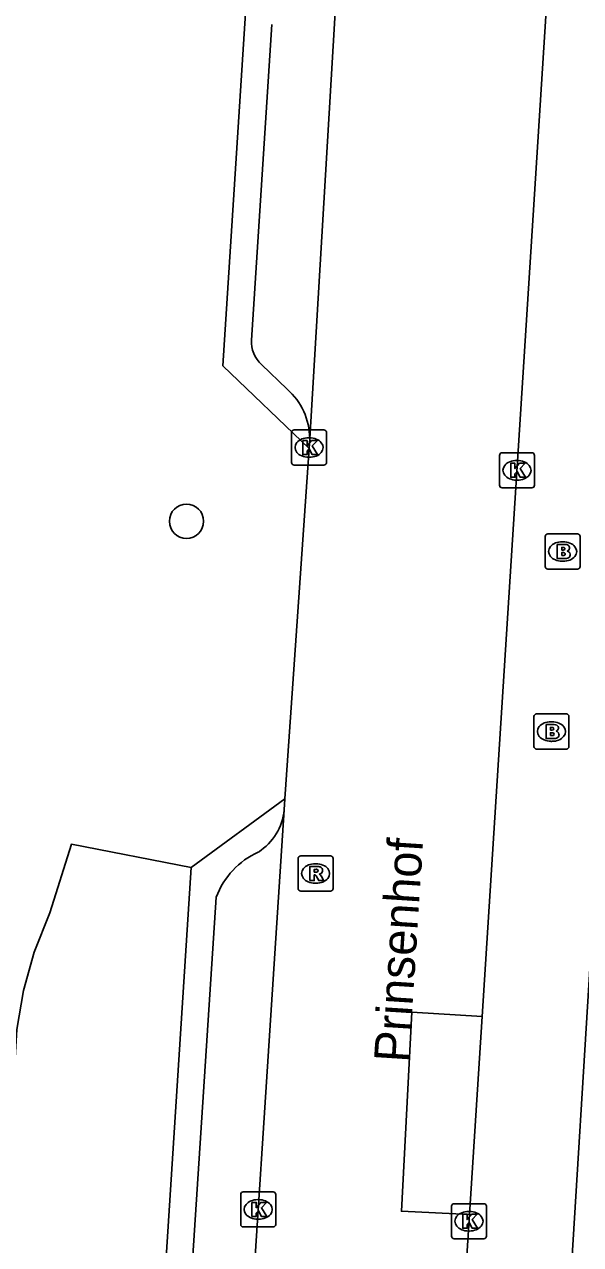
# Model space of a CAD drawing. Extents: x 159961 to 160856, y 382704 to 383353.
# Drawn here: x 160609.97 to 160625.85, y 382840.38 to 382875.2 of the extents above; entities that cross this region are included whole.
import ezdxf

# ---------------------------------------------------------------- set-up
doc = ezdxf.new("R2010")
doc.units = 0
for name, color, linetype in [('IMGEO_Boom', 7, 'Continuous'), ('IMGEO_Brandkraan', 7, 'Continuous'), ('IMGEO_Groenvoorziening', 7, 'Continuous'), ('IMGEO_Kolk', 7, 'Continuous'), ('IMGEO_Openbare_ruimte_label', 7, 'Continuous'), ('IMGEO_Rijbaan_lokaal_open', 7, 'Continuous'), ('IMGEO_Rioolput', 7, 'Continuous'), ('IMGEO_Voetpad_open', 7, 'Continuous')]:
    doc.layers.add(name, color=color, linetype=linetype)

msp = doc.modelspace()

# ---------------------------------------------------------------- linework, layer by layer
at = {"layer": 'IMGEO_Boom'}
msp.add_circle((160614.596, 382861.021), 0.489, dxfattribs=at)
at = {"layer": 'IMGEO_Brandkraan'}
for p, q in [((160624.836, 382859.731), (160624.836, 382860.583)), ((160624.911, 382860.657), (160625.763, 382860.657)), ((160625.324, 382860.437), (160625.349, 382860.437)), ((160625.837, 382860.583), (160625.837, 382859.731)), ((160625.763, 382859.657), (160624.911, 382859.657)), ((160625.347, 382859.877), (160625.322, 382859.877)), ((160624.591, 382855.521), (160625.443, 382855.521)), ((160624.516, 382854.595), (160624.516, 382855.447)), ((160625.004, 382855.301), (160625.029, 382855.301)), ((160625.517, 382855.447), (160625.517, 382854.595)), ((160625.443, 382854.521), (160624.591, 382854.521)), ((160625.027, 382854.741), (160625.002, 382854.741))]:
    msp.add_line(p, q, dxfattribs=at)
for points in [[(160624.836, 382859.731), (160624.836, 382860.583)], [(160624.911, 382860.657), (160625.763, 382860.657)], [(160625.184, 382860.357), (160625.184, 382859.957), (160625.397, 382859.957)], [(160625.415, 382860.357), (160625.184, 382860.357)], [(160625.837, 382860.583), (160625.837, 382859.731)], [(160625.363, 382860.276), (160625.309, 382860.276), (160625.309, 382860.2)], [(160625.309, 382860.2), (160625.362, 382860.2)], [(160625.371, 382860.124), (160625.309, 382860.124), (160625.309, 382860.043)], [(160625.309, 382860.043), (160625.371, 382860.043)], [(160625.763, 382859.657), (160624.911, 382859.657)], [(160624.591, 382855.521), (160625.443, 382855.521)], [(160624.516, 382854.595), (160624.516, 382855.447)], [(160624.864, 382855.221), (160624.864, 382854.821), (160625.077, 382854.821)], [(160625.095, 382855.221), (160624.864, 382855.221)], [(160625.043, 382855.14), (160624.989, 382855.14), (160624.989, 382855.064)], [(160625.517, 382855.447), (160625.517, 382854.595)], [(160624.989, 382855.064), (160625.042, 382855.064)], [(160625.051, 382854.988), (160624.989, 382854.988), (160624.989, 382854.907)], [(160624.989, 382854.907), (160625.051, 382854.907)], [(160625.443, 382854.521), (160624.591, 382854.521)]]:
    msp.add_lwpolyline(points, dxfattribs=at)
for centre, radius, start, end in [((160624.913, 382860.581), 0.0765, 91.552, 178.448), ((160624.913, 382860.581), 0.0765, 91.552, 178.448), ((160625.419, 382860.212), 0.145, 59.4692, 91.5367), ((160625.444, 382860.259), 0.0922, 285.5137, 58.1501), ((160625.761, 382860.581), 0.0765, 1.552, 88.448), ((160625.761, 382860.581), 0.0765, 1.552, 88.448), ((160625.364, 382860.238), 0.0379, 267.8285, 90.9355), ((160625.372, 382860.083), 0.0404, 269.8759, 90.5077), ((160625.449, 382860.067), 0.105, 301.3115, 78.989), ((160624.913, 382859.733), 0.0765, 181.552, 268.448), ((160624.913, 382859.733), 0.0765, 181.552, 268.448), ((160625.403, 382860.208), 0.251, 268.6676, 293.5347), ((160625.761, 382859.733), 0.0765, 271.552, 358.448), ((160625.761, 382859.733), 0.0765, 271.552, 358.448), ((160624.593, 382855.445), 0.0765, 91.552, 178.448), ((160624.593, 382855.445), 0.0765, 91.552, 178.448), ((160625.441, 382855.445), 0.0765, 1.552, 88.448), ((160625.441, 382855.445), 0.0765, 1.552, 88.448), ((160625.044, 382855.102), 0.0379, 267.8285, 90.9355), ((160625.099, 382855.076), 0.145, 59.4692, 91.5367), ((160625.124, 382855.123), 0.0922, 285.5137, 58.1501), ((160625.052, 382854.947), 0.0404, 269.8759, 90.5077), ((160625.083, 382855.072), 0.251, 268.6676, 293.5347), ((160625.129, 382854.931), 0.105, 301.3115, 78.989), ((160624.593, 382854.597), 0.0765, 181.552, 268.448), ((160624.593, 382854.597), 0.0765, 181.552, 268.448), ((160625.441, 382854.597), 0.0765, 271.552, 358.448), ((160625.441, 382854.597), 0.0765, 271.552, 358.448)]:
    msp.add_arc(centre, radius, start, end, dxfattribs=at)
for centre, major_axis, ratio, start_param, end_param in [((160625.323, 382860.157), (-0.387, 0.002), 0.722429, 4.712389, 7.853982), ((160625.348, 382860.157), (-0.39, 0.002), 0.717154, 1.570796, 4.712389), ((160625.003, 382855.021), (-0.387, 0.002), 0.722429, 4.712389, 7.853982), ((160625.028, 382855.021), (-0.39, 0.002), 0.717154, 1.570796, 4.712389)]:
    msp.add_ellipse(centre, major_axis=major_axis, ratio=ratio, start_param=start_param, end_param=end_param, dxfattribs=at)
at = {"layer": 'IMGEO_Groenvoorziening'}
msp.add_lwpolyline([(160601.528, 382813.411), (160601.58, 382813.752), (160601.524, 382815.216), (160601.773, 382816.66), (160602.317, 382818.02), (160603.033, 382819.117), (160607.251, 382823.714), (160607.533, 382824.104), (160607.967, 382824.962), (160608.26, 382826.337), (160609.182, 382837.25), (160609.683, 382845.386), (160609.753, 382846.515), (160609.94, 382847.631), (160610.243, 382848.721), (160610.693, 382849.85), (160611.309, 382851.803), (160614.727, 382851.14)], dxfattribs=at)
at = {"layer": 'IMGEO_Kolk'}
for p, q in [((160617.595, 382862.698), (160617.595, 382863.55)), ((160617.67, 382863.624), (160618.522, 382863.624)), ((160618.596, 382863.55), (160618.596, 382862.698)), ((160618.083, 382863.404), (160618.108, 382863.404)), ((160618.106, 382862.844), (160618.081, 382862.844)), ((160623.532, 382862.048), (160623.532, 382862.9)), ((160623.607, 382862.974), (160624.459, 382862.974)), ((160624.533, 382862.9), (160624.533, 382862.048)), ((160618.522, 382862.624), (160617.67, 382862.624)), ((160624.02, 382862.754), (160624.045, 382862.754)), ((160624.043, 382862.194), (160624.018, 382862.194)), ((160624.459, 382861.974), (160623.607, 382861.974)), ((160616.218, 382841.886), (160617.07, 382841.886)), ((160616.143, 382840.96), (160616.143, 382841.812)), ((160616.631, 382841.666), (160616.656, 382841.666)), ((160617.144, 382841.812), (160617.144, 382840.96)), ((160622.237, 382841.549), (160623.089, 382841.549)), ((160622.162, 382840.623), (160622.162, 382841.475)), ((160622.65, 382841.329), (160622.675, 382841.329)), ((160623.163, 382841.475), (160623.163, 382840.623)), ((160617.07, 382840.886), (160616.218, 382840.886)), ((160616.654, 382841.106), (160616.629, 382841.106)), ((160623.089, 382840.549), (160622.237, 382840.549)), ((160622.673, 382840.769), (160622.648, 382840.769))]:
    msp.add_line(p, q, dxfattribs=at)
for points in [[(160617.595, 382862.698), (160617.595, 382863.55)], [(160617.67, 382863.624), (160618.522, 382863.624)], [(160618.596, 382863.55), (160618.596, 382862.698)], [(160617.916, 382863.324), (160618.039, 382863.324), (160618.039, 382863.173), (160618.169, 382863.324), (160618.333, 382863.324), (160618.187, 382863.173), (160618.34, 382862.924), (160618.188, 382862.924), (160618.103, 382863.088), (160618.039, 382863.021), (160618.039, 382862.924), (160617.916, 382862.924), (160617.916, 382863.324)], [(160623.532, 382862.048), (160623.532, 382862.9)], [(160623.607, 382862.974), (160624.459, 382862.974)], [(160624.533, 382862.9), (160624.533, 382862.048)], [(160618.522, 382862.624), (160617.67, 382862.624)], [(160623.853, 382862.674), (160623.976, 382862.674), (160623.976, 382862.523), (160624.106, 382862.674), (160624.27, 382862.674), (160624.124, 382862.523), (160624.277, 382862.274), (160624.125, 382862.274), (160624.04, 382862.438), (160623.976, 382862.371), (160623.976, 382862.274), (160623.853, 382862.274), (160623.853, 382862.674)], [(160624.459, 382861.974), (160623.607, 382861.974)], [(160616.218, 382841.886), (160617.07, 382841.886)], [(160616.143, 382840.96), (160616.143, 382841.812)], [(160616.464, 382841.586), (160616.587, 382841.586), (160616.587, 382841.435), (160616.717, 382841.586), (160616.881, 382841.586), (160616.735, 382841.435), (160616.888, 382841.186), (160616.736, 382841.186), (160616.651, 382841.35), (160616.587, 382841.283), (160616.587, 382841.186), (160616.464, 382841.186), (160616.464, 382841.586)], [(160617.144, 382841.812), (160617.144, 382840.96)], [(160622.237, 382841.549), (160623.089, 382841.549)], [(160622.162, 382840.623), (160622.162, 382841.475)], [(160622.483, 382841.249), (160622.606, 382841.249), (160622.606, 382841.098), (160622.736, 382841.249), (160622.9, 382841.249), (160622.754, 382841.098), (160622.907, 382840.849), (160622.755, 382840.849), (160622.67, 382841.013), (160622.606, 382840.946), (160622.606, 382840.849), (160622.483, 382840.849), (160622.483, 382841.249)], [(160623.163, 382841.475), (160623.163, 382840.623)], [(160617.07, 382840.886), (160616.218, 382840.886)], [(160623.089, 382840.549), (160622.237, 382840.549)]]:
    msp.add_lwpolyline(points, dxfattribs=at)
for centre, start, end in [((160617.672, 382863.548), 91.552, 178.448), ((160617.672, 382863.548), 91.552, 178.448), ((160618.52, 382863.548), 1.552, 88.448), ((160618.52, 382863.548), 1.552, 88.448), ((160623.609, 382862.898), 91.552, 178.448), ((160623.609, 382862.898), 91.552, 178.448), ((160624.457, 382862.898), 1.552, 88.448), ((160624.457, 382862.898), 1.552, 88.448), ((160617.672, 382862.7), 181.552, 268.448), ((160617.672, 382862.7), 181.552, 268.448), ((160618.52, 382862.7), 271.552, 358.448), ((160618.52, 382862.7), 271.552, 358.448), ((160623.609, 382862.05), 181.552, 268.448), ((160623.609, 382862.05), 181.552, 268.448), ((160624.457, 382862.05), 271.552, 358.448), ((160624.457, 382862.05), 271.552, 358.448), ((160616.22, 382841.81), 91.552, 178.448), ((160616.22, 382841.81), 91.552, 178.448), ((160617.068, 382841.81), 1.552, 88.448), ((160617.068, 382841.81), 1.552, 88.448), ((160622.239, 382841.473), 91.552, 178.448), ((160622.239, 382841.473), 91.552, 178.448), ((160623.087, 382841.473), 1.552, 88.448), ((160623.087, 382841.473), 1.552, 88.448), ((160616.22, 382840.962), 181.552, 268.448), ((160616.22, 382840.962), 181.552, 268.448), ((160617.068, 382840.962), 271.552, 358.448), ((160617.068, 382840.962), 271.552, 358.448), ((160622.239, 382840.625), 181.552, 268.448), ((160622.239, 382840.625), 181.552, 268.448), ((160623.087, 382840.625), 271.552, 358.448), ((160623.087, 382840.625), 271.552, 358.448)]:
    msp.add_arc(centre, 0.0765, start, end, dxfattribs=at)
for centre, major_axis, ratio, start_param, end_param in [((160618.082, 382863.124), (-0.387, 0.002), 0.722429, 4.712389, 7.853982), ((160618.107, 382863.124), (-0.39, 0.002), 0.717154, 1.570796, 4.712389), ((160624.019, 382862.474), (-0.387, 0.002), 0.722429, 4.712389, 7.853982), ((160624.044, 382862.474), (-0.39, 0.002), 0.717154, 1.570796, 4.712389), ((160616.63, 382841.386), (-0.387, 0.002), 0.722429, 4.712389, 7.853982), ((160616.655, 382841.386), (-0.39, 0.002), 0.717154, 1.570796, 4.712389), ((160622.649, 382841.049), (-0.387, 0.002), 0.722429, 4.712389, 7.853982), ((160622.674, 382841.049), (-0.39, 0.002), 0.717154, 1.570796, 4.712389)]:
    msp.add_ellipse(centre, major_axis=major_axis, ratio=ratio, start_param=start_param, end_param=end_param, dxfattribs=at)
at = {"layer": 'IMGEO_Rijbaan_lokaal_open'}
for points in [[(160625.366, 382883.36), (160623.034, 382846.889)], [(160618.961, 382877.626), (160618.115, 382863.386)], [(160618.115, 382863.386), (160618.095, 382863.099)], [(160618.095, 382863.099), (160617.405, 382853.1)], [(160617.405, 382853.1), (160617.385, 382852.787)], [(160617.385, 382852.787), (160616.065, 382832.433)], [(160622.673, 382841.238), (160620.735, 382841.335), (160621.028, 382847.017), (160623.034, 382846.889)], [(160622.673, 382841.238), (160620.296, 382804.062)]]:
    msp.add_lwpolyline(points, dxfattribs=at)
at = {"layer": 'IMGEO_Rioolput'}
for p, q in [((160617.782, 382850.544), (160617.782, 382851.396)), ((160617.857, 382851.47), (160618.709, 382851.47)), ((160618.783, 382851.396), (160618.783, 382850.544)), ((160618.27, 382851.25), (160618.295, 382851.25)), ((160618.293, 382850.69), (160618.268, 382850.69)), ((160618.709, 382850.47), (160617.857, 382850.47))]:
    msp.add_line(p, q, dxfattribs=at)
for points in [[(160617.782, 382850.544), (160617.782, 382851.396)], [(160617.857, 382851.47), (160618.709, 382851.47)], [(160618.783, 382851.396), (160618.783, 382850.544)], [(160618.371, 382851.168), (160618.119, 382851.17), (160618.119, 382850.77)], [(160618.297, 382851.089), (160618.243, 382851.089), (160618.243, 382851.008)], [(160618.243, 382851.008), (160618.295, 382851.008)], [(160618.119, 382850.77), (160618.243, 382850.77), (160618.243, 382850.932), (160618.254, 382850.932)], [(160618.301, 382850.903), (160618.372, 382850.77), (160618.512, 382850.77), (160618.447, 382850.896)], [(160618.709, 382850.47), (160617.857, 382850.47)]]:
    msp.add_lwpolyline(points, dxfattribs=at)
for centre, radius, start, end in [((160617.859, 382851.394), 0.0765, 91.552, 178.448), ((160617.859, 382851.394), 0.0765, 91.552, 178.448), ((160618.707, 382851.394), 0.0765, 1.552, 88.448), ((160618.707, 382851.394), 0.0765, 1.552, 88.448), ((160618.279, 382851.197), 0.19, 274.7715, 282.9687), ((160618.303, 382850.993), 0.0964, 77.0061, 93.1865), ((160618.317, 382851.05), 0.0378, 276.6634, 79.6772), ((160618.37, 382851.058), 0.109, 350.3612, 89.416), ((160618.368, 382851.058), 0.112, 277.5842, 350.9817), ((160618.352, 382850.843), 0.108, 29.5134, 73.7905), ((160618.253, 382850.879), 0.0533, 26.0293, 88.6989), ((160617.859, 382850.546), 0.0765, 181.552, 268.448), ((160617.859, 382850.546), 0.0765, 181.552, 268.448), ((160618.707, 382850.546), 0.0765, 271.552, 358.448), ((160618.707, 382850.546), 0.0765, 271.552, 358.448)]:
    msp.add_arc(centre, radius, start, end, dxfattribs=at)
for centre, major_axis, ratio, start_param, end_param in [((160618.269, 382850.97), (-0.387, 0.002), 0.722429, 4.712389, 7.853982), ((160618.294, 382850.97), (-0.39, 0.002), 0.717154, 1.570796, 4.712389)]:
    msp.add_ellipse(centre, major_axis=major_axis, ratio=ratio, start_param=start_param, end_param=end_param, dxfattribs=at)
at = {"layer": 'IMGEO_Voetpad_open'}
for points in [[(160628.385, 382885.22), (160623.291, 382802.488), (160622.253, 382790.875), (160621.956, 382786.436)], [(160616.307, 382875.97), (160615.637, 382865.457), (160618.095, 382863.099)], [(160616.448, 382866.189), (160617.036, 382875.196)], [(160617.471, 382864.785), (160616.742, 382865.494)], [(160614.727, 382851.14), (160617.405, 382853.1)], [(160616.05, 382832.203), (160613.667, 382834.528), (160614.727, 382851.14)], [(160614.467, 382835.236), (160615.446, 382850.296)], [(160623.034, 382846.889), (160622.673, 382841.238)]]:
    msp.add_lwpolyline(points, dxfattribs=at)
for centre, radius, start, end in [((160617.319, 382866.148), 0.872, 177.3046, 228.5542), ((160616.248, 382863.374), 1.867, 0.3557, 49.0803), ((160615.789, 382852.935), 1.603, 302.3676, 354.7041), ((160617.579, 382849.506), 2.275, 114.1896, 159.6808)]:
    msp.add_arc(centre, radius, start, end, dxfattribs=at)

# ---------------------------------------------------------------- texts
at = {"layer": 'IMGEO_Openbare_ruimte_label'}
msp.add_text('Prinsenhof', height=1, rotation=86.3307, dxfattribs=at).set_placement((160620.946, 382845.56))

doc.saveas('drawing.dxf')
